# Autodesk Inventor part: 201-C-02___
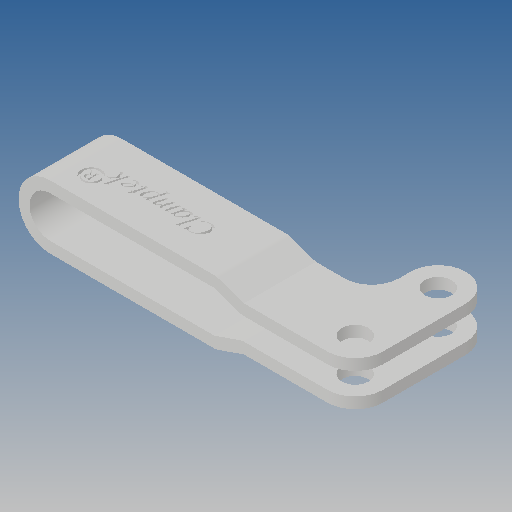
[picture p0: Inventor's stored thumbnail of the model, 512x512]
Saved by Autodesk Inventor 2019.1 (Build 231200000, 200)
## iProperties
Created: 2010-06
Part Number: 201-C-02___
Material: Ogólny
Document SubType Name: Modeling
Designer: CADENGINEERING4
Density: 1 g/cm^3
Appearance: Domyślna
Author: CADENGINEERING4
Revision Number: ANY
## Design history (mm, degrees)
feature "NONE"
node "Bryła1"
